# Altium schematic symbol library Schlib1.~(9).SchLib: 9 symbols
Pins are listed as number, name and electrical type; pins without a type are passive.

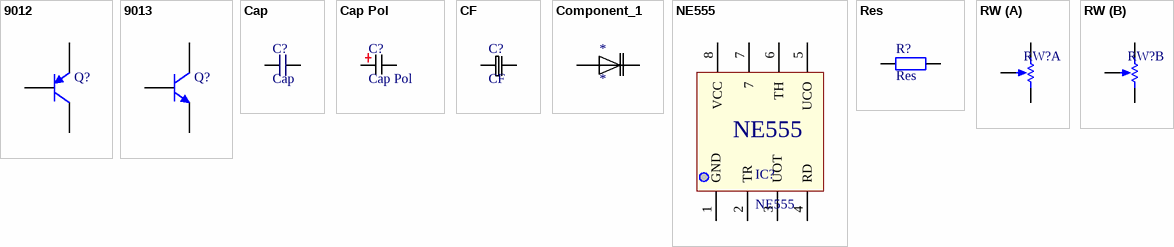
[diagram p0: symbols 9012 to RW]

## 9012
designator Q?  (value not drawn)
PNP General Purpose Amplifier
pins: 1 E, 2 B, 3 C

## 9013
designator Q?  (value not drawn)
NPN General Purpose Amplifier
pins: 1 E, 2 B, 3 C

## Cap
designator C?
pins: 1, 2

## Cap Pol
designator C?
pins: 1, 2

## CF
designator C?
pins: 1, 2

## Component_1
designator *

## NE555
designator IC?
pins: 1 GND, 2 TR, 3 UOT, 4 RD, 5 UCO, 6 TH, 7, 8 VCC

## Res
designator R?
Resistor; Value: 1K
pins: 1, 2

## RW
designator RW?  (value not drawn)
part A pins: 1 TOP, 2 TAP, 3 BOT
part B pins: 4 TOP, 5 TAP, 6 BOT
